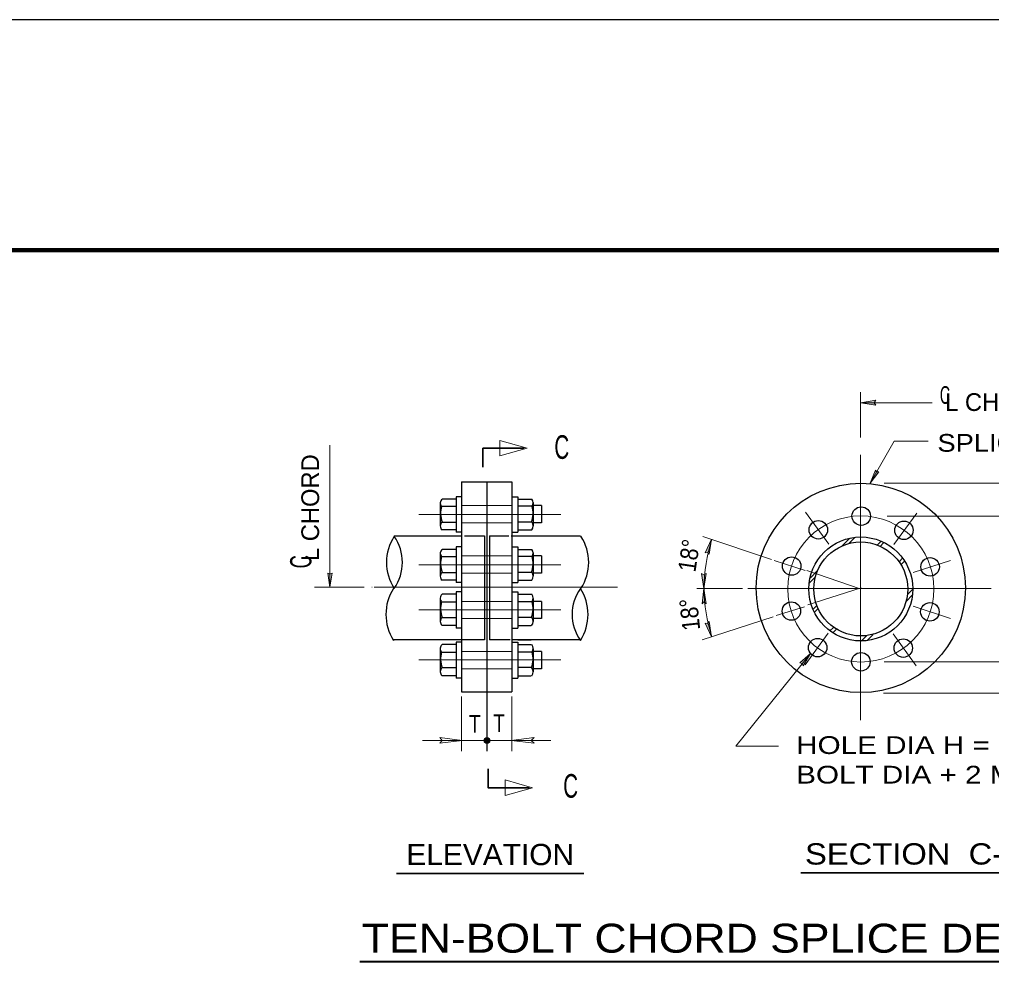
# Model space of a CAD drawing. Extents: x 312601.858 to 312602.699, y 144420.109 to 144420.704.
# Drawn here: x 312602.2889 to 312602.4533, y 144420.5442 to 144420.7035 of the extents above; entities that cross this region are included whole.
import ezdxf
from ezdxf.enums import TextEntityAlignment as Align

# ---------------------------------------------------------------- set-up
doc = ezdxf.new("R2010")
doc.units = 0
doc.header["$LTSCALE"] = 0.0012
for name, pattern in [('DOT_DASHED', [7.7, 5, -1.2, 0.3, -1.2]), ('LONG_DASHED', [7.5, 6, -1.5]), ('MEDIUM_DASHED', [4.5, 3, -1.5])]:
    doc.linetypes.add(name, pattern=pattern)
for name, color, linetype, lineweight in [('1', 7, 'Continuous', 25), ('2', 7, 'Continuous', 13), ('39', 7, 'Continuous', 13), ('9', 7, 'Continuous', 13)]:
    doc.layers.add(name, color=color, linetype=linetype, lineweight=lineweight)

msp = doc.modelspace()

# ---------------------------------------------------------------- hatches: boundary and pattern name
at = {"layer": '1'}
msp.add_hatch(color=256, dxfattribs=at).paths.add_polyline_path([(312602.368505, 144420.581575, 1), (312602.367485, 144420.581575, 1)])
at = {"layer": '39'}
for points in [[(312602.4335, 144420.6387), (312602.4338, 144420.6383), (312602.4312, 144420.6387), (312602.4338, 144420.6391)], [(312602.4339, 144420.627), (312602.4343, 144420.627), (312602.4328, 144420.6251), (312602.4337, 144420.6273)], [(312602.4053, 144420.6134), (312602.4049, 144420.6133), (312602.406, 144420.6156), (312602.4056, 144420.6131)], [(312602.3414, 144420.6097), (312602.3418, 144420.6099), (312602.3414, 144420.6075), (312602.3411, 144420.6099)], [(312602.3414, 144420.6097), (312602.3418, 144420.6099), (312602.3414, 144420.6075), (312602.3411, 144420.6099)], [(312602.4047, 144420.6096), (312602.4051, 144420.6098), (312602.4047, 144420.6073), (312602.4043, 144420.6098)], [(312602.4047, 144420.605), (312602.4044, 144420.6047), (312602.4047, 144420.6073), (312602.4051, 144420.6047)], [(312602.4053, 144420.6013), (312602.4056, 144420.6017), (312602.406, 144420.5991), (312602.4049, 144420.6014)], [(312602.4213, 144420.5946), (312602.4209, 144420.5947), (312602.4227, 144420.5963), (312602.4215, 144420.5942)]]:
    msp.add_hatch(color=256, dxfattribs=at).paths.add_polyline_path(points)

# ---------------------------------------------------------------- linework, layer by layer
at = {"layer": '1', "lineweight": 13}
for p, q in [((312602.4312, 144420.6328), (312602.4312, 144420.6405)), ((312602.4312, 144420.6387), (312602.4433, 144420.6387)), ((312602.3414, 144420.6075), (312602.3414, 144420.6315)), ((312602.4328, 144420.6251), (312602.4369, 144420.6322)), ((312602.4352, 144420.6251), (312602.4796, 144420.6251)), ((312602.3772, 144420.6211), (312602.3772, 144420.6213)), ((312602.4357, 144420.6195), (312602.4636, 144420.6195)), ((312602.4161, 144420.6122), (312602.4045, 144420.6161)), ((312602.3772, 144420.6126), (312602.3772, 144420.6128)), ((312602.4311, 144420.6072), (312602.4221, 144420.6103)), ((312602.3388, 144420.6075), (312602.3472, 144420.6075)), ((312602.4035, 144420.6073), (312602.4112, 144420.6073)), ((312602.4313, 144420.6074), (312602.4223, 144420.6045)), ((312602.3772, 144420.6049), (312602.3772, 144420.6051)), ((312602.4164, 144420.6025), (312602.4044, 144420.5986)), ((312602.3772, 144420.5964), (312602.3772, 144420.5966)), ((312602.4101, 144420.5806), (312602.4227, 144420.5963)), ((312602.4352, 144420.5949), (312602.4636, 144420.5949)), ((312602.3637, 144420.589), (312602.3637, 144420.5798)), ((312602.3722, 144420.589), (312602.3722, 144420.5798)), ((312602.4351, 144420.5896), (312602.4796, 144420.5896)), ((312602.3571, 144420.5816), (312602.3788, 144420.5816)), ((312602.4101, 144420.5806), (312602.4173, 144420.5806))]:
    msp.add_line(p, q, dxfattribs=at)
at = {"layer": '1', "linetype": 'DOT_DASHED', "lineweight": 13}
for p, q in [((312602.4312, 144420.585), (312602.4312, 144420.6299)), ((312602.3805, 144420.6198), (312602.3565, 144420.6198)), ((312602.3635, 144420.6198), (312602.3594, 144420.6198)), ((312602.4258, 144420.6148), (312602.4219, 144420.6202)), ((312602.4368, 144420.6147), (312602.4407, 144420.62)), ((312602.3805, 144420.6113), (312602.3565, 144420.6113)), ((312602.3635, 144420.6113), (312602.3594, 144420.6113)), ((312602.4218, 144420.6103), (312602.4166, 144420.612)), ((312602.4401, 144420.61), (312602.4464, 144420.612)), ((312602.3485, 144420.6075), (312602.3486, 144420.6075)), ((312602.3489, 144420.6075), (312602.3901, 144420.6075)), ((312602.4121, 144420.6073), (312602.4533, 144420.6073)), ((312602.3805, 144420.6037), (312602.3565, 144420.6037)), ((312602.4217, 144420.6042), (312602.4169, 144420.6027)), ((312602.4401, 144420.6043), (312602.4464, 144420.6022)), ((312602.4257, 144420.5997), (312602.4218, 144420.5944)), ((312602.4367, 144420.5996), (312602.4406, 144420.5942)), ((312602.3805, 144420.5952), (312602.3565, 144420.5952)), ((312602.3725, 144420.5952), (312602.3766, 144420.5952))]:
    msp.add_line(p, q, dxfattribs=at)
at = {"layer": '1'}
for p, q in [((312602.3637, 144420.6253), (312602.3722, 144420.6253)), ((312602.368, 144420.6253), (312602.368, 144420.5798)), ((312602.3722, 144420.6253), (312602.3722, 144420.6162)), ((312602.3628, 144420.6228), (312602.3628, 144420.6168)), ((312602.3637, 144420.6228), (312602.3628, 144420.6228)), ((312602.3722, 144420.6228), (312602.3732, 144420.6228)), ((312602.3732, 144420.6228), (312602.3732, 144420.6168)), ((312602.3601, 144420.6218), (312602.3601, 144420.6179)), ((312602.3603, 144420.6212), (312602.3628, 144420.6212)), ((312602.3628, 144420.6224), (312602.3604, 144420.6224)), ((312602.3732, 144420.6224), (312602.3756, 144420.6224)), ((312602.3756, 144420.6212), (312602.3732, 144420.6212)), ((312602.3758, 144420.6218), (312602.3758, 144420.6179)), ((312602.3772, 144420.6213), (312602.3758, 144420.6213)), ((312602.3772, 144420.6213), (312602.3772, 144420.6184)), ((312602.3604, 144420.6185), (312602.3628, 144420.6185)), ((312602.3756, 144420.6185), (312602.3732, 144420.6185)), ((312602.3772, 144420.6184), (312602.3758, 144420.6184)), ((312602.3628, 144420.6172), (312602.3604, 144420.6172)), ((312602.3637, 144420.6168), (312602.3628, 144420.6168)), ((312602.3722, 144420.6168), (312602.3732, 144420.6168)), ((312602.3732, 144420.6172), (312602.3756, 144420.6172)), ((312602.3523, 144420.6162), (312602.3637, 144420.6162)), ((312602.3721, 144420.6162), (312602.3838, 144420.6162)), ((312602.3722, 144420.6162), (312602.3722, 144420.5898)), ((312602.3628, 144420.6139), (312602.3604, 144420.6139)), ((312602.3628, 144420.6143), (312602.3628, 144420.6083)), ((312602.3637, 144420.6143), (312602.3628, 144420.6143)), ((312602.3722, 144420.6143), (312602.3732, 144420.6143)), ((312602.3732, 144420.6143), (312602.3732, 144420.6083)), ((312602.3732, 144420.6139), (312602.3756, 144420.6139)), ((312602.3758, 144420.6133), (312602.3758, 144420.6094)), ((312602.3603, 144420.6127), (312602.3628, 144420.6127)), ((312602.3756, 144420.6127), (312602.3732, 144420.6127)), ((312602.3772, 144420.6128), (312602.3758, 144420.6128)), ((312602.3772, 144420.6128), (312602.3772, 144420.6099)), ((312602.3604, 144420.61), (312602.3628, 144420.61)), ((312602.3756, 144420.61), (312602.3732, 144420.61)), ((312602.3772, 144420.6099), (312602.3758, 144420.6099)), ((312602.3628, 144420.6087), (312602.3604, 144420.6087)), ((312602.3637, 144420.6083), (312602.3628, 144420.6083)), ((312602.3722, 144420.6083), (312602.3732, 144420.6083)), ((312602.3732, 144420.6087), (312602.3756, 144420.6087)), ((312602.3628, 144420.6067), (312602.3628, 144420.6006)), ((312602.3637, 144420.6067), (312602.3628, 144420.6067)), ((312602.3722, 144420.6067), (312602.3732, 144420.6067)), ((312602.3732, 144420.6067), (312602.3732, 144420.6006)), ((312602.3601, 144420.6056), (312602.3601, 144420.6017)), ((312602.3603, 144420.605), (312602.3628, 144420.605)), ((312602.3628, 144420.6063), (312602.3604, 144420.6063)), ((312602.3732, 144420.6063), (312602.3756, 144420.6063)), ((312602.3756, 144420.605), (312602.3732, 144420.605)), ((312602.3758, 144420.6056), (312602.3758, 144420.6017)), ((312602.3772, 144420.6051), (312602.3758, 144420.6051)), ((312602.3772, 144420.6051), (312602.3772, 144420.6022)), ((312602.3604, 144420.6024), (312602.3628, 144420.6024)), ((312602.3756, 144420.6024), (312602.3732, 144420.6024)), ((312602.3772, 144420.6022), (312602.3758, 144420.6022)), ((312602.3628, 144420.601), (312602.3604, 144420.601)), ((312602.3637, 144420.6006), (312602.3628, 144420.6006)), ((312602.3722, 144420.6006), (312602.3732, 144420.6006)), ((312602.3732, 144420.601), (312602.3755, 144420.601)), ((312602.3637, 144420.5986), (312602.3522, 144420.5986)), ((312602.3628, 144420.5986), (312602.3604, 144420.5986)), ((312602.3628, 144420.5982), (312602.3628, 144420.5921)), ((312602.3637, 144420.5982), (312602.3628, 144420.5982)), ((312602.3839, 144420.5986), (312602.3722, 144420.5986)), ((312602.3722, 144420.5982), (312602.3732, 144420.5982)), ((312602.3732, 144420.5986), (312602.3755, 144420.5986)), ((312602.3732, 144420.5982), (312602.3732, 144420.5921)), ((312602.3601, 144420.5971), (312602.3601, 144420.5932)), ((312602.3603, 144420.5965), (312602.3628, 144420.5965)), ((312602.3628, 144420.5978), (312602.3604, 144420.5978)), ((312602.3732, 144420.5978), (312602.3755, 144420.5978)), ((312602.3756, 144420.5965), (312602.3732, 144420.5965)), ((312602.3758, 144420.5971), (312602.3758, 144420.5932)), ((312602.3772, 144420.5966), (312602.3758, 144420.5966)), ((312602.3772, 144420.5966), (312602.3772, 144420.5937)), ((312602.3604, 144420.5939), (312602.3628, 144420.5939)), ((312602.3755, 144420.5939), (312602.3732, 144420.5939)), ((312602.3772, 144420.5937), (312602.3758, 144420.5937)), ((312602.3628, 144420.5925), (312602.3604, 144420.5925)), ((312602.3637, 144420.5921), (312602.3628, 144420.5921)), ((312602.3722, 144420.5921), (312602.3732, 144420.5921)), ((312602.3732, 144420.5925), (312602.3755, 144420.5925)), ((312602.3637, 144420.5898), (312602.3722, 144420.5898))]:
    msp.add_line(p, q, dxfattribs=at)
at = {"layer": '1', "linetype": 'LONG_DASHED', "lineweight": 13}
for p, q in [((312602.3722, 144420.6213), (312602.3637, 144420.6213)), ((312602.3722, 144420.6184), (312602.3637, 144420.6184)), ((312602.3722, 144420.6128), (312602.3637, 144420.6128)), ((312602.3722, 144420.6099), (312602.3637, 144420.6099)), ((312602.3722, 144420.6051), (312602.3637, 144420.6051)), ((312602.3722, 144420.6022), (312602.3637, 144420.6022)), ((312602.3722, 144420.5966), (312602.3637, 144420.5966))]:
    msp.add_line(p, q, dxfattribs=at)
at = {"layer": '1', "linetype": 'LONG_DASHED'}
for p, q in [((312602.3642, 144420.6162), (312602.3676, 144420.6162)), ((312602.3676, 144420.6162), (312602.3676, 144420.5986)), ((312602.3684, 144420.6162), (312602.3684, 144420.5986)), ((312602.3684, 144420.6162), (312602.3717, 144420.6162)), ((312602.3676, 144420.5986), (312602.3637, 144420.5986)), ((312602.3719, 144420.5986), (312602.3684, 144420.5986))]:
    msp.add_line(p, q, dxfattribs=at)
at = {"layer": '1', "linetype": 'MEDIUM_DASHED', "lineweight": 13}
msp.add_line((312602.3722, 144420.5937), (312602.3638, 144420.5937), dxfattribs=at)
at = {"layer": '1', "lineweight": 35}
for points in [[(312602.3743, 144420.631), (312602.3673, 144420.631), (312602.3673, 144420.6278)], [(312602.3752, 144420.5736), (312602.3682, 144420.5736), (312602.3682, 144420.5768)]]:
    msp.add_lwpolyline(points, dxfattribs=at)
at = {"layer": '1'}
msp.add_lwpolyline([(312602.3637, 144420.6253), (312602.3637, 144420.6236), (312602.3637, 144420.6162), (312602.3637, 144420.5915), (312602.3637, 144420.5898)], dxfattribs=at)
at = {"layer": '1', "lineweight": 13}
for points in [[(312602.36, 144420.5821), (312602.3638, 144420.5816), (312602.36, 144420.5811), (312602.3604, 144420.5816)], [(312602.376, 144420.5821), (312602.3721, 144420.5816), (312602.376, 144420.5811), (312602.3755, 144420.5816)]]:
    msp.add_lwpolyline(points, close=True, dxfattribs=at)
at = {"layer": '1'}
for centre, radius in [((312602.43123, 144420.60737), 0.017693), ((312602.431298, 144420.619512), 0.00156), ((312602.424048, 144420.6172), 0.00156), ((312602.438521, 144420.61712), 0.00156), ((312602.43123, 144420.6072), 0.008788), ((312602.43123, 144420.6072), 0.007942), ((312602.419542, 144420.611069), 0.00156), ((312602.44296, 144420.61094), 0.00156), ((312602.4195, 144420.60346), 0.00156), ((312602.442918, 144420.603331), 0.00156), ((312602.423939, 144420.59728), 0.00156), ((312602.438412, 144420.5972), 0.00156), ((312602.431247, 144420.594888), 0.00156)]:
    msp.add_circle(centre, radius, dxfattribs=at)
at = {"layer": '1', "linetype": 'DOT_DASHED', "lineweight": 13}
msp.add_circle((312602.43123, 144420.6072), 0.012354, dxfattribs=at)
at = {"layer": '1', "lineweight": 13}
msp.add_circle((312602.367995, 144420.581575), 0.00051, dxfattribs=at)
at = {"layer": '1'}
for centre, radius, start, end in [((312602.360978, 144420.621772), 0.000881, 134.49444, 222.90534), ((312602.364325, 144420.61998), 0.004169, 163.41266, 200.28256), ((312602.371635, 144420.61998), 0.004169, 339.71744, 16.58734), ((312602.374695, 144420.621765), 0.001105, 327.52435, 35.07587), ((312602.361028, 144420.617855), 0.00093, 133.00499, 226.99501), ((312602.374695, 144420.617855), 0.001105, 322.02013, 37.97987), ((312602.360978, 144420.613272), 0.000881, 134.49444, 222.90534), ((312602.374695, 144420.613265), 0.001105, 327.52435, 35.07587), ((312602.364325, 144420.61148), 0.004169, 163.41266, 200.28256), ((312602.371635, 144420.61148), 0.004169, 339.20371, 16.58734), ((312602.361028, 144420.609355), 0.00093, 133.00499, 226.99501), ((312602.374695, 144420.609355), 0.001105, 322.02013, 37.97987), ((312602.360995, 144420.605628), 0.000898, 132.0101, 222.48567), ((312602.364325, 144420.60383), 0.004169, 163.41266, 200.28256), ((312602.371635, 144420.60383), 0.004169, 339.71744, 16.58734), ((312602.374695, 144420.605615), 0.001105, 327.52435, 37.97987), ((312602.361015, 144420.601705), 0.000921, 132.38578, 227.61422), ((312602.374695, 144420.601705), 0.001105, 320.35648, 37.97987), ((312602.360995, 144420.597128), 0.000898, 132.0101, 222.48567), ((312602.364325, 144420.59533), 0.004169, 163.41266, 200.28256), ((312602.371635, 144420.59533), 0.004169, 339.71744, 16.58734), ((312602.374695, 144420.597115), 0.001105, 327.52435, 37.97987), ((312602.361033, 144420.593205), 0.000933, 133.23403, 226.76597), ((312602.374695, 144420.593205), 0.001105, 322.02013, 37.97987)]:
    msp.add_arc(centre, radius, start, end, dxfattribs=at)
at = {"layer": '1', "lineweight": 13}
for start, end in [(161.91393, 180.18375), (180.18228, 198.11113)]:
    msp.add_arc((312602.43123, 144420.60737), 0.026504, start, end, dxfattribs=at)
at = {"layer": '2'}
for p, q in [((312602.4426, 144420.6322), (312602.4369, 144420.6322)), ((312602.4281, 144420.6145), (312602.4294, 144420.6158)), ((312602.4292, 144420.6149), (312602.4302, 144420.6159)), ((312602.434, 144420.6146), (312602.4347, 144420.6153)), ((312602.4345, 144420.6144), (312602.4351, 144420.615)), ((312602.4377, 144420.6118), (312602.4383, 144420.6124)), ((312602.4381, 144420.6114), (312602.4386, 144420.6119)), ((312602.4227, 144420.6091), (312602.4239, 144420.6103)), ((312602.4225, 144420.6082), (312602.4236, 144420.6093)), ((312602.4392, 144420.6063), (312602.44, 144420.6071)), ((312602.4389, 144420.6051), (312602.44, 144420.6062)), ((312602.4232, 144420.6038), (312602.4238, 144420.6044)), ((312602.4234, 144420.6033), (312602.424, 144420.6039)), ((312602.426, 144420.6001), (312602.4266, 144420.6007)), ((312602.4265, 144420.5998), (312602.4271, 144420.6004)), ((312602.4313, 144420.5984), (312602.4322, 144420.5993)), ((312602.4323, 144420.5985), (312602.4333, 144420.5995))]:
    msp.add_line(p, q, dxfattribs=at)
at = {"layer": '2', "linetype": 'DOT_DASHED'}
msp.add_line((312602.4312, 144420.5873), (312602.4312, 144420.6268), dxfattribs=at)
at = {"layer": '2', "lineweight": 25}
msp.add_line((312602.3601, 144420.6133), (312602.3601, 144420.6094), dxfattribs=at)
at = {"layer": '2', "lineweight": 35}
for p, q in [((312602.3527, 144420.5591), (312602.3844, 144420.5591)), ((312602.4211, 144420.5592), (312602.4612, 144420.5592))]:
    msp.add_line(p, q, dxfattribs=at)
at = {"layer": '2', "lineweight": 40}
msp.add_line((312602.3465, 144420.5442), (312602.4718, 144420.5442), dxfattribs=at)
at = {"layer": '2', "lineweight": 25}
for centre, radius, start, end in [((312602.359092, 144420.6117), 0.008093, 147.06517, 212.93482), ((312602.346086, 144420.6117), 0.007614, 324.69975, 35.30025), ((312602.377108, 144420.6117), 0.008093, 327.06517, 32.93482), ((312602.358992, 144420.6029), 0.008093, 147.06517, 212.93482), ((312602.390014, 144420.6029), 0.007614, 144.69975, 215.30025), ((312602.377008, 144420.6029), 0.008093, 327.06517, 32.93482)]:
    msp.add_arc(centre, radius, start, end, dxfattribs=at)
at = {"layer": '39', "lineweight": 25}
msp.add_line((312601.8578, 144420.7035), (312602.6988, 144420.7035), dxfattribs=at)
at = {"layer": '39', "lineweight": 158}
msp.add_line((312601.9088, 144420.6645), (312602.6838, 144420.6645), dxfattribs=at)
at = {"layer": '39'}
for points in [[(312602.4335, 144420.6387), (312602.4338, 144420.6383), (312602.4312, 144420.6387), (312602.4338, 144420.6391)], [(312602.4339, 144420.627), (312602.4343, 144420.627), (312602.4328, 144420.6251), (312602.4337, 144420.6273)], [(312602.4053, 144420.6134), (312602.4049, 144420.6133), (312602.406, 144420.6156), (312602.4056, 144420.6131)], [(312602.3414, 144420.6097), (312602.3418, 144420.6099), (312602.3414, 144420.6075), (312602.3411, 144420.6099)], [(312602.3414, 144420.6097), (312602.3418, 144420.6099), (312602.3414, 144420.6075), (312602.3411, 144420.6099)], [(312602.4047, 144420.6096), (312602.4051, 144420.6098), (312602.4047, 144420.6073), (312602.4043, 144420.6098)], [(312602.4047, 144420.605), (312602.4044, 144420.6047), (312602.4047, 144420.6073), (312602.4051, 144420.6047)], [(312602.4053, 144420.6013), (312602.4056, 144420.6017), (312602.406, 144420.5991), (312602.4049, 144420.6014)], [(312602.4213, 144420.5946), (312602.4209, 144420.5947), (312602.4227, 144420.5963), (312602.4215, 144420.5942)]]:
    msp.add_lwpolyline(points, close=True, dxfattribs=at)
at = {"layer": '9'}
for points in [[(312602.3702, 144420.6297), (312602.3748, 144420.631), (312602.3702, 144420.6323)], [(312602.3711, 144420.5723), (312602.3757, 144420.5736), (312602.3711, 144420.5749)]]:
    msp.add_lwpolyline(points, close=True, dxfattribs=at)

# ---------------------------------------------------------------- texts
at = {"layer": '2'}
for s, width, p in [('C', 0.6, (312602.4446, 144420.6385)), ('HOLE DIA H = ', 1.25, (312602.4203, 144420.5793)), ('BOLT DIA + 2 MM', 1.25, (312602.4203, 144420.5743))]:
    msp.add_text(s, height=0.003, dxfattribs=dict(at, width=width)).set_placement(p)
msp.add_text('L CHORD', height=0.003, dxfattribs=at).set_placement((312602.4455, 144420.6373))
for s, height, width, p in [('C', 0.004, 0.65, (312602.38065, 144420.6292)), ('SPLICE PLATE', 0.003, 1.15, (312602.46035, 144420.6304)), ('T', 0.003, 0.8, (312602.36595, 144420.5829)), ('T', 0.003, 0.8, (312602.37005, 144420.583)), ('C', 0.004, 0.65, (312602.38215, 144420.5719)), ('ELEVATION', 0.0036, 1.05, (312602.36855, 144420.5605)), ('SECTION  C-C', 0.0036, 1.15, (312602.44055, 144420.5606)), ('TEN-BOLT CHORD SPLICE DETAIL', 0.0049, 1.15, (312602.409, 144420.5457))]:
    msp.add_text(s, height=height, dxfattribs=dict(at, width=width)).set_placement(p, align=Align.CENTER)
msp.add_text('L CHORD', height=0.003, rotation=90, dxfattribs=at).set_placement((312602.3396, 144420.62095), align=Align.CENTER)
for s, height, rotation, width, p in [('18°', 0.003, 81.444, 0.9, (312602.403655, 144420.612627)), ('C', 0.0036, 90, 0.65, (312602.3383, 144420.6118)), ('18°', 0.003, 96.187, 0.9, (312602.403781, 144420.603038))]:
    msp.add_text(s, height=height, rotation=rotation, dxfattribs=dict(at, width=width)).set_placement(p, align=Align.CENTER)

doc.saveas('drawing.dxf')
